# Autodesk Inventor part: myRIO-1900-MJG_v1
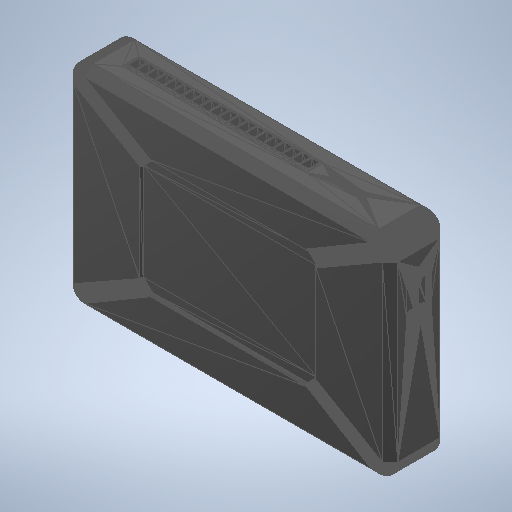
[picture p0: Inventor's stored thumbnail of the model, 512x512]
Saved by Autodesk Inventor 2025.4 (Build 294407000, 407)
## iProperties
Created: 2026-09
Part Number: myRIO-1900-MJG_v1
Material: Genérico
Document SubType Name: Modeling
Designer: usuario
Density: 1 g/cm^3
Appearance: Valor por defecto
Author: usuario
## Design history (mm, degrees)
node "myRIO-1900-MJG_v1"
  node "MeshFeature1"
